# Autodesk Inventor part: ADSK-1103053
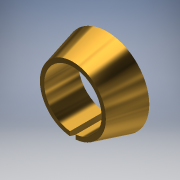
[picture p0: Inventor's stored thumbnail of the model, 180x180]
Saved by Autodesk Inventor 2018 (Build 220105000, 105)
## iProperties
Shininess: 50.0
Length Units: 11272
Angle Units: 11279
Time Units: 11290
Mass Units: 11286
Length Display Precision: 4
Angle Display Precision: 2
Compacted: True
Created: 2000-08
Part Number: ADSK-1103053
Document SubType Name: Modeling
Description: TAPER NUT
Mass: 1.42288 g
Surface Area: 3.58073 cm^2
Volume: 0.16799 cm^3
Density: 8.47 g/cm^3
Material: Brass, Soft Yellow
Appearance: Brass - Satin
Density: 0.0
Volumn: 0.0
Area: 0.0
PropertySet Name: Model Information
Control State: 0
Master: False
Checked Out: False
Author: Autodesk, Inc.
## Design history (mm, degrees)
node "Extrusion1" dims "d1" = 4.7625, "d2" = -15 deg
  sketch "Sketch3"
    geometry: C1 r 5.874 at (0, 0)
    constraints: 1 centre point
    dimensions: "d0" = 11.7475 diameter of C1
node "Extrusion2" dims "d4" = 6.35, "d5" = 0
  sketch "Sketch4"
    geometry: C1 r 5.874 at (0, 0) reference; C2 r 4 at (0, 0)
    constraints: 1 centre point, 1 coincident
    dimensions: "d3" = 8 diameter of C2
node "Extrusion3" dims "d8" = 6.35, "d9" = 0
  sketch "Sketch5"
    geometry: L1 (0.406, 0)-(-0.406, 0); L2 (-0.406, 0)-(-0.406, -5.874); L3 (-0.406, -5.874)-(0.406, -5.874); L4 (0.406, -5.874)-(0.406, 0); C1 r 4 at (0, 0) reference; C2 r 5.874 at (0, 0) reference
    constraints: 8 end point, 2 parallel, 1 horizontal, 1 midpoint, 1 perpendicular, 1 tangent
    dimensions: "d6" = 0.8128 distance of L2.end L3.end; "d7" = 0.4064 distance from line of C1.centre L4 (= 0.5 x d6)
body "Solid1"
